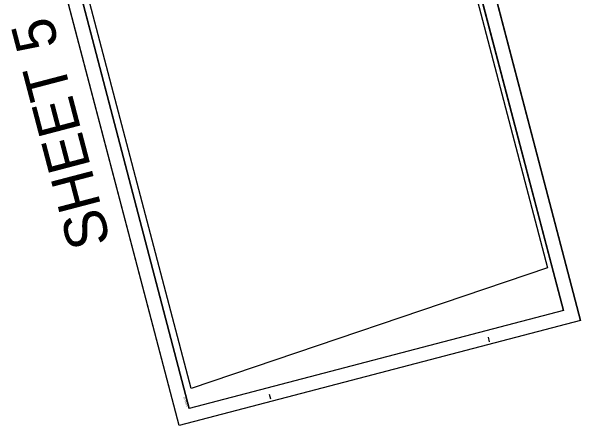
# Model space of a CAD drawing. Extents: x 1366394 to 1367903, y 879298 to 881221.
# Drawn here: x 1366394 to 1367903, y 879298 to 880397 of the extents above; entities that cross this region are included whole.
import ezdxf

# ---------------------------------------------------------------- set-up
doc = ezdxf.new("R2010")
doc.units = 0
for name, color, linetype in [('Exist Property Line Text', 7, 'Continuous'), ('Exist Right of Way Line', 7, 'Continuous'), ('Exist Structure Minor Footbridge Terminator', 7, 'Continuous'), ('Exist Utilities Water AG Line', 7, 'Continuous'), ('Scratch_Level_0', 7, 'Continuous'), ('Scratch_Level_4', 7, 'Continuous')]:
    doc.layers.add(name, color=color, linetype=linetype)

msp = doc.modelspace()

# ---------------------------------------------------------------- linework, layer by layer
at = {"layer": 'Exist Property Line Text'}
for p, q in [((1367902.6, 879576.7), (1367471.6, 881221.1)), ((1366838.5, 879297.8), (1366407.5, 880942.3)), ((1367902.6, 879576.7), (1366838.5, 879297.8))]:
    msp.add_line(p, q, dxfattribs=at)
at = {"layer": 'Exist Right of Way Line'}
for p, q in [((1367856.8, 879603.4), (1367444.8, 881175.3)), ((1366453.3, 880915.5), (1366865.3, 879343.6)), ((1367856.8, 879603.4), (1366865.3, 879343.6)), ((1367661.5, 879520.3), (1367658.3, 879532.3)), ((1366850.4, 879370.7), (1366850.4, 879370.7)), ((1367081.1, 879368.1), (1367077.9, 879380.2))]:
    msp.add_line(p, q, dxfattribs=at)
at = {"layer": 'Exist Structure Minor Footbridge Terminator'}
msp.add_lwpolyline([(1366870, 879396.1), (1366503.2, 880795.9), (1367465.8, 881048.1), (1367814.9, 879716.1)], close=True, dxfattribs=at)
at = {"layer": 'Exist Utilities Water AG Line'}
msp.add_line((1367902.6, 879576.7), (1367902.6, 879576.7), dxfattribs=at)
at = {"layer": 'Scratch_Level_0'}
msp.add_lwpolyline([(1366865.3, 879343.6), (1366478.7, 880818.8), (1367470.2, 881078.6), (1367856.8, 879603.4)], close=True, dxfattribs=at)
at = {"layer": 'Scratch_Level_4'}
msp.add_lwpolyline([(1366838.5, 879297.8), (1366407.5, 880942.3), (1367471.6, 881221.1), (1367902.6, 879576.7)], close=True, dxfattribs=at)

# ---------------------------------------------------------------- texts
at = {"layer": 'Exist Right of Way Line'}
msp.add_text('11/14/23', height=5, rotation=104.6851, dxfattribs=at).set_placement((1366862, 879348.8))
at = {"layer": 'Exist Structure Minor Footbridge Terminator'}
msp.add_text('SHEET 5', height=112.11, rotation=104.6851, dxfattribs=at).set_placement((1366657.6, 879783.9))

doc.saveas('drawing.dxf')
